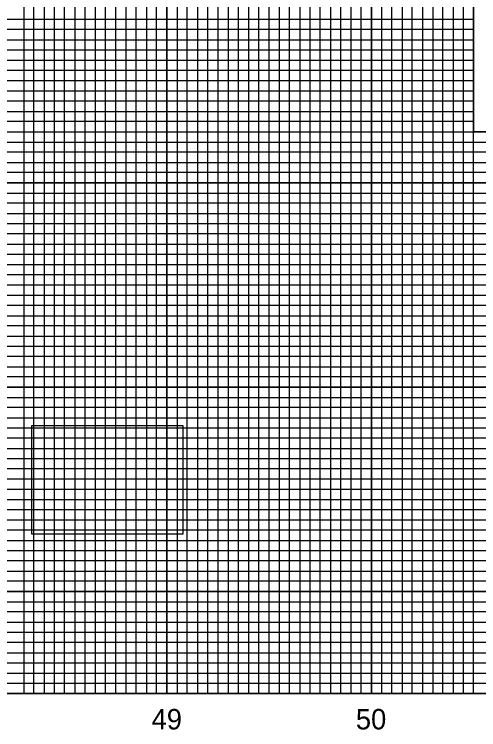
# Model space of a CAD drawing. Extents: x 1779926 to 1781610, y 620464 to 621564.
# Drawn here: x 1781168.3 to 1781395.5, y 621021.5 to 621371.7 of the extents above; entities that cross this region are included whole.
import ezdxf

# ---------------------------------------------------------------- set-up
doc = ezdxf.new("R2010")
doc.units = 0
for name, color, linetype in [('Exist Vertical Profile Horizontal Axis Label Major', 7, 'Continuous'), ('Old_Level_58', 7, 'Continuous'), ('Prop Grid Mask', 7, 'Continuous'), ('Scratch_Level_0', 7, 'Continuous'), ('Sheet DOT Grid CELL', 7, 'Continuous'), ('Sheet Layout Profile Border Port 1', 7, 'Continuous'), ('Sheet Profile CELL', 7, 'Continuous'), ('Sheet Profile Grid Major CELL', 7, 'Continuous'), ('Sheet Profile Grid Middle CELL', 7, 'Continuous'), ('Sheet Profile Grid Minor CELL', 7, 'Continuous')]:
    doc.layers.add(name, color=color, linetype=linetype)

msp = doc.modelspace()

# ---------------------------------------------------------------- linework, layer by layer
at = {"layer": 'Old_Level_58'}
msp.add_lwpolyline([(1781392.96, 621378.14), (1781592.95, 621378.14), (1781592.95, 621314.19), (1781392.96, 621314.19)], close=True, dxfattribs=at)
at = {"layer": 'Prop Grid Mask'}
msp.add_lwpolyline([(1781176.92, 621170.45), (1781250.71, 621170.45), (1781250.71, 621117.29), (1781176.92, 621117.29)], close=True, dxfattribs=at)
at = {"layer": 'Scratch_Level_0'}
msp.add_lwpolyline([(1780142.96, 621039.19), (1780142.96, 621539.19), (1781392.96, 621539.19), (1781392.96, 621314.19), (1781542.96, 621314.19), (1781542.96, 621039.19)], close=True, dxfattribs=at)
at = {"layer": 'Sheet DOT Grid CELL'}
for p, q in [((1781192.96, 621039.19), (1781192.96, 621539.19)), ((1781242.96, 621039.19), (1781242.96, 621539.19)), ((1781292.96, 621039.19), (1781292.96, 621539.19)), ((1781342.96, 621039.19), (1781342.96, 621539.19)), ((1781392.96, 621039.19), (1781392.96, 621401.64)), ((1781392.91, 621339.19), (1780092.96, 621339.19)), ((1781592.96, 621289.19), (1780092.96, 621289.19)), ((1781592.96, 621239.19), (1780092.96, 621239.19)), ((1781592.96, 621189.19), (1780092.96, 621189.19)), ((1781592.96, 621139.19), (1780092.96, 621139.19)), ((1781592.96, 621089.19), (1780092.96, 621089.19))]:
    msp.add_line(p, q, dxfattribs=at)
at = {"layer": 'Sheet Layout Profile Border Port 1'}
msp.add_lwpolyline([(1780142.96, 621378.14), (1780142.96, 621039.19), (1781542.96, 621039.19), (1781542.96, 621314.19)], dxfattribs=at)
at = {"layer": 'Sheet Profile CELL'}
msp.add_line((1780092.96, 621039.19), (1781592.96, 621039.19), dxfattribs=at)
at = {"layer": 'Sheet Profile Grid Major CELL'}
for points in [[(1781142.96, 621039.19), (1781192.96, 621039.19), (1781192.96, 621539.19), (1781242.96, 621539.19), (1781242.96, 621039.19), (1781292.96, 621039.19), (1781292.96, 621539.19), (1781342.96, 621539.19), (1781342.96, 621039.19), (1781392.96, 621039.19), (1781392.96, 621539.19), (1781419.26, 621539.19)], [(1781392.91, 621339.19), (1780092.96, 621339.19), (1780092.96, 621289.19), (1781592.96, 621289.19)], [(1781592.96, 621239.19), (1780092.96, 621239.19), (1780092.96, 621189.19), (1781592.96, 621189.19)], [(1781592.96, 621139.19), (1780092.96, 621139.19), (1780092.96, 621139.19), (1780092.96, 621089.19), (1781592.96, 621089.19)]]:
    msp.add_lwpolyline(points, dxfattribs=at)
at = {"layer": 'Sheet Profile Grid Middle CELL'}
for points in [[(1781167.96, 621039.19), (1781217.96, 621039.19), (1781217.96, 621539.19), (1781267.96, 621539.19), (1781267.96, 621039.19), (1781317.96, 621039.19), (1781317.96, 621539.19), (1781367.96, 621539.19), (1781367.96, 621039.19), (1781417.96, 621039.19), (1781417.96, 621314.19)], [(1781392.91, 621364.19), (1780092.96, 621364.19), (1780092.96, 621314.19), (1781417.96, 621314.19)], [(1781592.96, 621264.19), (1780092.96, 621264.19), (1780092.96, 621214.19), (1781592.96, 621214.19)], [(1781592.96, 621164.19), (1780092.96, 621164.19), (1780092.96, 621114.19), (1781592.96, 621114.19)], [(1781592.96, 621064.19), (1780092.96, 621064.19)]]:
    msp.add_lwpolyline(points, dxfattribs=at)
at = {"layer": 'Sheet Profile Grid Minor CELL'}
for p, q in [((1781392.96, 621354.19), (1780142.96, 621354.19)), ((1780142.96, 621349.19), (1781392.96, 621349.19)), ((1781392.91, 621329.19), (1780142.96, 621329.19)), ((1780142.96, 621324.19), (1781392.91, 621324.19)), ((1781542.96, 621304.19), (1780142.96, 621304.19)), ((1780142.96, 621299.19), (1781542.96, 621299.19)), ((1781542.96, 621294.19), (1780142.96, 621294.19)), ((1780142.96, 621284.19), (1781542.96, 621284.19)), ((1781542.96, 621279.19), (1780142.96, 621279.19)), ((1780142.96, 621274.19), (1781542.96, 621274.19)), ((1781542.96, 621269.19), (1780142.96, 621269.19)), ((1780142.96, 621259.19), (1781542.96, 621259.19)), ((1781542.96, 621254.19), (1780142.96, 621254.19)), ((1780142.96, 621249.19), (1781542.96, 621249.19)), ((1781542.96, 621244.19), (1780142.96, 621244.19)), ((1780142.96, 621234.19), (1781542.96, 621234.19)), ((1781542.96, 621229.19), (1780142.96, 621229.19)), ((1780142.96, 621224.19), (1781542.96, 621224.19)), ((1781542.96, 621219.19), (1780142.96, 621219.19)), ((1780142.96, 621209.19), (1781542.96, 621209.19)), ((1781542.96, 621204.19), (1780142.96, 621204.19)), ((1780142.96, 621199.19), (1781542.96, 621199.19)), ((1781542.96, 621194.19), (1780142.96, 621194.19)), ((1780142.96, 621184.19), (1781542.96, 621184.19)), ((1781542.96, 621179.19), (1780142.96, 621179.19)), ((1780142.96, 621174.19), (1781542.96, 621174.19)), ((1781542.96, 621169.19), (1780142.96, 621169.19)), ((1780142.96, 621159.19), (1781542.96, 621159.19)), ((1781542.96, 621154.19), (1780142.96, 621154.19)), ((1781542.96, 621149.19), (1780142.96, 621149.19)), ((1781542.96, 621144.19), (1780142.96, 621144.19)), ((1780142.96, 621134.19), (1781542.96, 621134.19)), ((1781542.96, 621129.19), (1780142.96, 621129.19)), ((1780142.96, 621124.19), (1781542.96, 621124.19)), ((1781542.96, 621119.19), (1780142.96, 621119.19)), ((1780142.96, 621109.19), (1781542.96, 621109.19)), ((1781542.96, 621104.19), (1780142.96, 621104.19)), ((1780142.96, 621099.19), (1781542.96, 621099.19)), ((1781542.96, 621094.19), (1780142.96, 621094.19)), ((1780142.96, 621084.19), (1781542.96, 621084.19)), ((1781542.96, 621079.19), (1780142.96, 621079.19)), ((1780142.96, 621074.19), (1781542.96, 621074.19)), ((1781542.96, 621069.19), (1780142.96, 621069.19)), ((1780142.96, 621059.19), (1781542.96, 621059.19)), ((1781542.96, 621054.19), (1780142.96, 621054.19)), ((1780142.96, 621049.19), (1781542.96, 621049.19))]:
    msp.add_line(p, q, dxfattribs=at)
for points in [[(1781172.96, 621539.19), (1781172.96, 621039.19), (1781177.96, 621039.19), (1781177.96, 621539.19)], [(1781182.96, 621539.19), (1781182.96, 621039.19), (1781187.96, 621039.19), (1781187.96, 621539.19)], [(1781197.96, 621539.19), (1781197.96, 621039.19), (1781202.96, 621039.19), (1781202.96, 621539.19)], [(1781207.96, 621539.19), (1781207.96, 621039.19), (1781212.96, 621039.19), (1781212.96, 621539.19)], [(1781222.96, 621539.19), (1781222.96, 621039.19), (1781227.96, 621039.19), (1781227.96, 621539.19)], [(1781232.96, 621539.19), (1781232.96, 621039.19), (1781237.96, 621039.19), (1781237.96, 621539.19)], [(1781247.96, 621539.19), (1781247.96, 621039.19), (1781252.96, 621039.19), (1781252.96, 621539.19)], [(1781257.96, 621539.19), (1781257.96, 621039.19), (1781262.96, 621039.19), (1781262.96, 621539.19)], [(1781272.96, 621539.19), (1781272.96, 621039.19), (1781277.96, 621039.19), (1781277.96, 621539.19)], [(1781282.96, 621539.19), (1781282.96, 621039.19)], [(1781282.96, 621039.19), (1781287.96, 621039.19), (1781287.96, 621539.19)], [(1781297.96, 621539.19), (1781297.96, 621039.19), (1781302.96, 621039.19), (1781302.96, 621539.19)], [(1781307.96, 621539.19), (1781307.96, 621039.19), (1781312.96, 621039.19), (1781312.96, 621539.19)], [(1781322.96, 621539.19), (1781322.96, 621039.19), (1781327.96, 621039.19), (1781327.96, 621539.19)], [(1781332.96, 621539.19), (1781332.96, 621039.19), (1781337.96, 621039.19), (1781337.96, 621539.19)], [(1781347.96, 621539.19), (1781347.96, 621039.19), (1781352.96, 621039.19), (1781352.96, 621539.19)], [(1781357.96, 621539.19), (1781357.96, 621039.19), (1781362.96, 621039.19), (1781362.96, 621539.19)], [(1781372.96, 621539.19), (1781372.96, 621039.19), (1781377.96, 621039.19), (1781377.96, 621539.19)], [(1781382.96, 621539.19), (1781382.96, 621039.19), (1781387.96, 621039.19), (1781387.96, 621539.19)], [(1781392.91, 621369.19), (1780142.96, 621369.19), (1780142.96, 621359.19), (1781392.91, 621359.19)], [(1781392.91, 621344.19), (1780142.96, 621344.19), (1780142.96, 621334.19), (1781392.91, 621334.19)], [(1781392.91, 621319.19), (1780142.96, 621319.19), (1780142.96, 621309.19), (1781542.96, 621309.19)], [(1781542.96, 621044.19), (1780142.96, 621044.19)]]:
    msp.add_lwpolyline(points, dxfattribs=at)

# ---------------------------------------------------------------- texts
at = {"layer": 'Exist Vertical Profile Horizontal Axis Label Major'}
for s, p in [('49', (1781235.47, 621021.69)), ('50', (1781335.39, 621021.69))]:
    msp.add_text(s, height=10, dxfattribs=at).set_placement(p)

doc.saveas('drawing.dxf')
